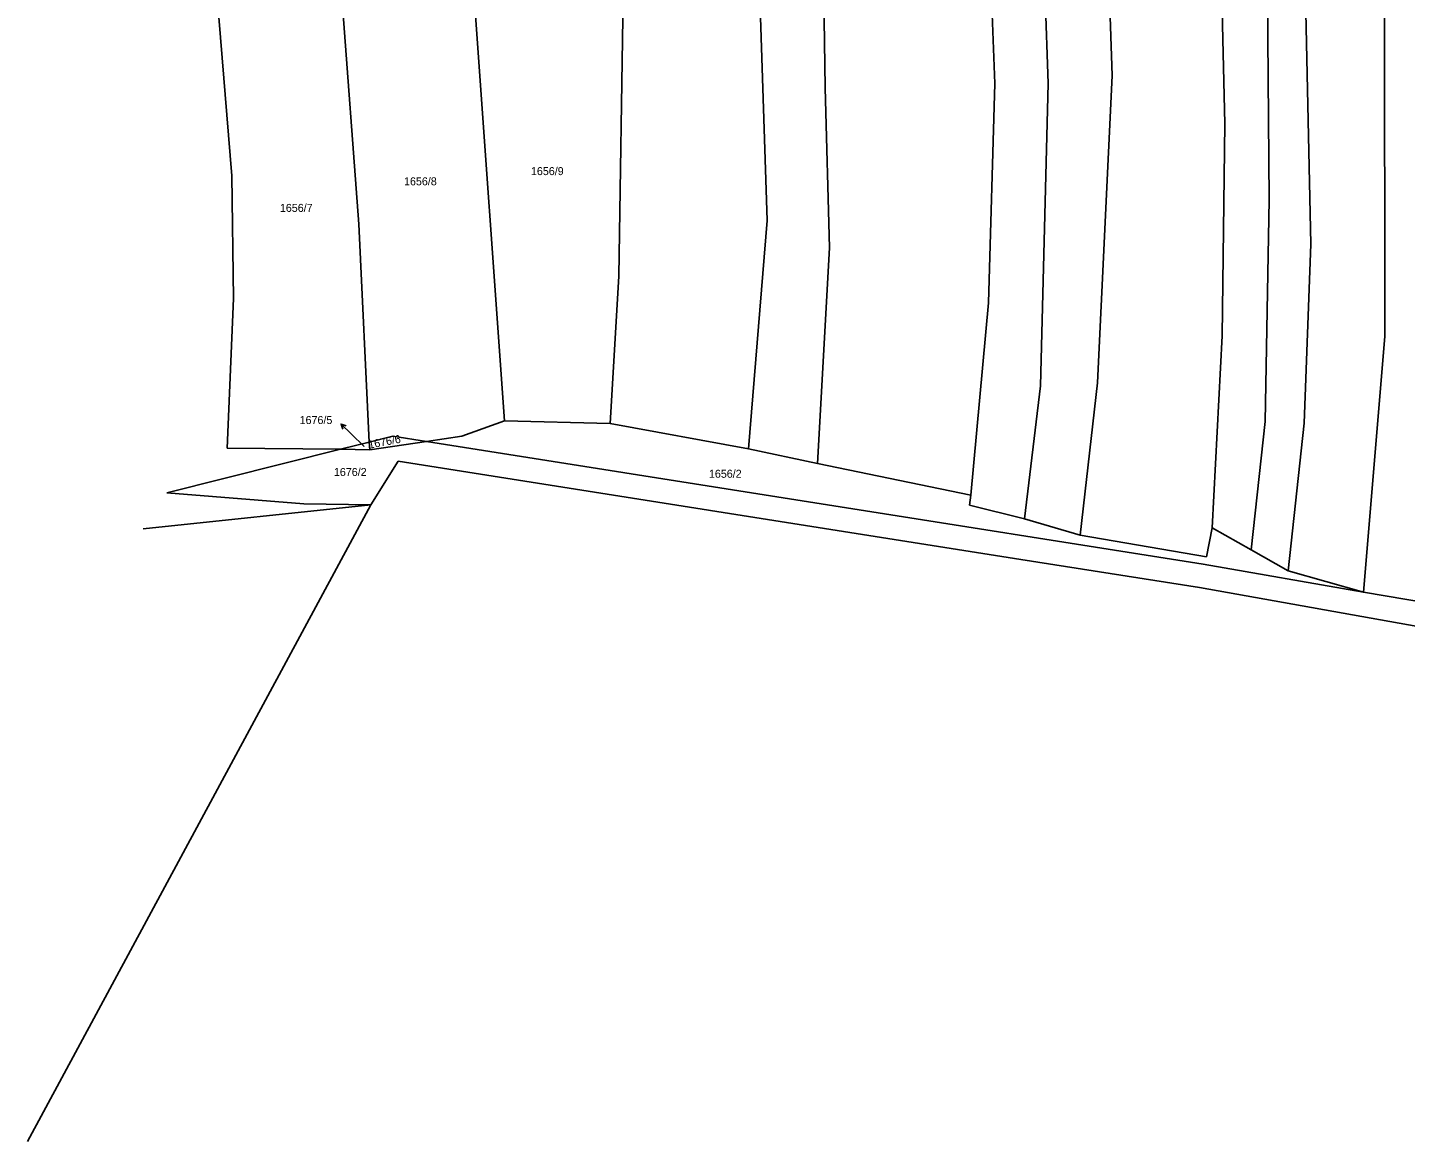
# Model space of a CAD drawing. Extents: x -763296 to -761805, y -1153670 to -1152034.
# Drawn here: x -763205.5 to -762912.8, y -1152989.4 to -1152752.7 of the extents above; entities that cross this region are included whole.
import ezdxf

# ---------------------------------------------------------------- set-up
doc = ezdxf.new("R2010")
doc.units = 0
for name, color, linetype in [('Vrstva 1', 7, 'Continuous'), ('Vrstva 13', 7, 'Continuous'), ('Vrstva 16', 7, 'Continuous'), ('Vrstva 18', 7, 'Continuous'), ('Vrstva 6', 7, 'Continuous')]:
    doc.layers.add(name, color=color, linetype=linetype)

msp = doc.modelspace()

# ---------------------------------------------------------------- linework, layer by layer
at = {"layer": 'Vrstva 1'}
for p, q in [((-763132.89, -1152840.8), (-763138.98, -1152842.32)), ((-763127.86, -1152839.55), (-763132.89, -1152840.8)), ((-763120.75, -1152840.67), (-763127.86, -1152839.55)), ((-762955.75, -1152866.75), (-763120.75, -1152840.67)), ((-763138.98, -1152842.32), (-763175.87, -1152851.53)), ((-763180.91, -1152859.2), (-763132.57, -1152854.08)), ((-762921.7, -1152872.64), (-762955.75, -1152866.75)), ((-762907.88, -1152875.02), (-762921.7, -1152872.64))]:
    msp.add_line(p, q, dxfattribs=at)
at = {"layer": 'Vrstva 13'}
for p, q in [((-763132.57, -1152854.08), (-763126.78, -1152844.85)), ((-763126.78, -1152844.85), (-762994.49, -1152865.71)), ((-763205.48, -1152989.37), (-763132.57, -1152854.08)), ((-762994.49, -1152865.71), (-762956.53, -1152871.69)), ((-762956.53, -1152871.69), (-762792.7, -1152901.01))]:
    msp.add_line(p, q, dxfattribs=at)
at = {"layer": 'Vrstva 16'}
for p in [(-763138.886, -1152836.953), (-763133.99, -1152841.74)]:
    msp.add_line(p, (-763136.74, -1152839.05), dxfattribs=at)
msp.add_lwpolyline([(-763138.52, -1152838.01), (-763138.886, -1152836.953), (-763137.821, -1152837.295)], dxfattribs=at)
at = {"layer": 'Vrstva 6'}
for p, q in [((-762951.17, -1152773.14), (-762953.58, -1152668.14)), ((-762975.11, -1152762.91), (-762977.04, -1152700.29)), ((-762988.65, -1152764.58), (-762990.82, -1152705.37)), ((-763048.38, -1152793.73), (-763050.86, -1152715.94)), ((-762932.91, -1152798.75), (-762934.49, -1152721.82)), ((-763036.03, -1152765.53), (-763036.66, -1152725.61)), ((-763104.2, -1152836.3), (-763111.73, -1152730.09)), ((-763001.47, -1152728.76), (-762999.98, -1152764.63)), ((-763135.14, -1152794.51), (-763139.48, -1152735.36)), ((-762941.74, -1152789.3), (-762942.16, -1152734.1)), ((-762917.2, -1152818.33), (-762917.24, -1152734.89)), ((-763162.09, -1152784.23), (-763165.36, -1152743.95)), ((-763078.89, -1152742.27), (-763079.9, -1152805.54)), ((-762999.98, -1152764.63), (-763001.39, -1152811.23)), ((-762990.29, -1152828.81), (-762988.65, -1152764.58)), ((-762978.2, -1152828.22), (-762975.11, -1152762.91)), ((-763035.14, -1152799.54), (-763036.03, -1152765.53)), ((-762951.75, -1152818.23), (-762951.17, -1152773.14)), ((-763161.7, -1152810.28), (-763162.09, -1152784.23)), ((-762942.56, -1152836.41), (-762941.74, -1152789.3)), ((-763132.89, -1152840.8), (-763135.14, -1152794.51)), ((-763052.37, -1152842.24), (-763048.38, -1152793.73)), ((-763037.66, -1152845.34), (-763035.14, -1152799.54)), ((-762934.29, -1152836.75), (-762932.91, -1152798.75)), ((-763079.9, -1152805.54), (-763081.75, -1152836.85)), ((-763163.08, -1152842.05), (-763161.7, -1152810.28)), ((-763001.39, -1152811.23), (-763005.13, -1152852.03)), ((-762953.86, -1152858.97), (-762951.75, -1152818.23)), ((-762917.2, -1152818.33), (-762921.7, -1152872.64)), ((-762993.73, -1152857.11), (-762990.29, -1152828.81)), ((-762981.86, -1152860.53), (-762978.2, -1152828.22)), ((-763113.2, -1152839.55), (-763104.2, -1152836.3)), ((-763104.2, -1152836.3), (-763081.75, -1152836.85)), ((-763081.75, -1152836.85), (-763052.37, -1152842.24)), ((-762945.58, -1152863.68), (-762942.56, -1152836.41)), ((-762937.69, -1152868.13), (-762934.29, -1152836.75)), ((-763132.77, -1152842.46), (-763132.89, -1152840.8)), ((-763132.77, -1152842.46), (-763120.75, -1152840.67)), ((-763120.75, -1152840.67), (-763113.2, -1152839.55)), ((-763163.08, -1152842.05), (-763138.98, -1152842.32)), ((-763138.98, -1152842.32), (-763132.77, -1152842.46)), ((-763052.37, -1152842.24), (-763037.66, -1152845.34)), ((-763037.66, -1152845.34), (-763005.13, -1152852.03)), ((-763175.87, -1152851.53), (-763146.81, -1152853.92)), ((-763005.13, -1152852.03), (-763005.4, -1152854.17)), ((-763146.81, -1152853.92), (-763132.57, -1152854.08)), ((-763005.4, -1152854.17), (-762993.73, -1152857.11)), ((-762993.73, -1152857.11), (-762981.86, -1152860.53)), ((-762955.05, -1152865.16), (-762953.86, -1152858.97)), ((-762953.86, -1152858.97), (-762945.58, -1152863.68)), ((-762981.86, -1152860.53), (-762955.05, -1152865.16)), ((-762945.58, -1152863.68), (-762937.69, -1152868.13)), ((-762937.69, -1152868.13), (-762921.7, -1152872.64))]:
    msp.add_line(p, q, dxfattribs=at)

# ---------------------------------------------------------------- texts
at = {"layer": 'Vrstva 16'}
msp.add_text('1676/5', height=1.7, dxfattribs=at).set_placement((-763147.69, -1152836.95))
at = {"layer": 'Vrstva 18'}
for s, height, p in [('1656/9', 1.7, (-763098.551, -1152784.06)), ('1656/8', 1.7, (-763125.511, -1152786.23)), ('1656/7', 1.7, (-763151.881, -1152791.88)), ('1676/5', 0.1, (-763134.212, -1152841.74)), ('1676/2', 1.7, (-763140.408, -1152847.99)), ('1656/2', 1.7, (-763060.745, -1152848.36))]:
    msp.add_text(s, height=height, dxfattribs=at).set_placement(p)
msp.add_text('1676/6', height=1.7, rotation=10.8862, dxfattribs=at).set_placement((-763132.917, -1152842.205))

doc.saveas('drawing.dxf')
